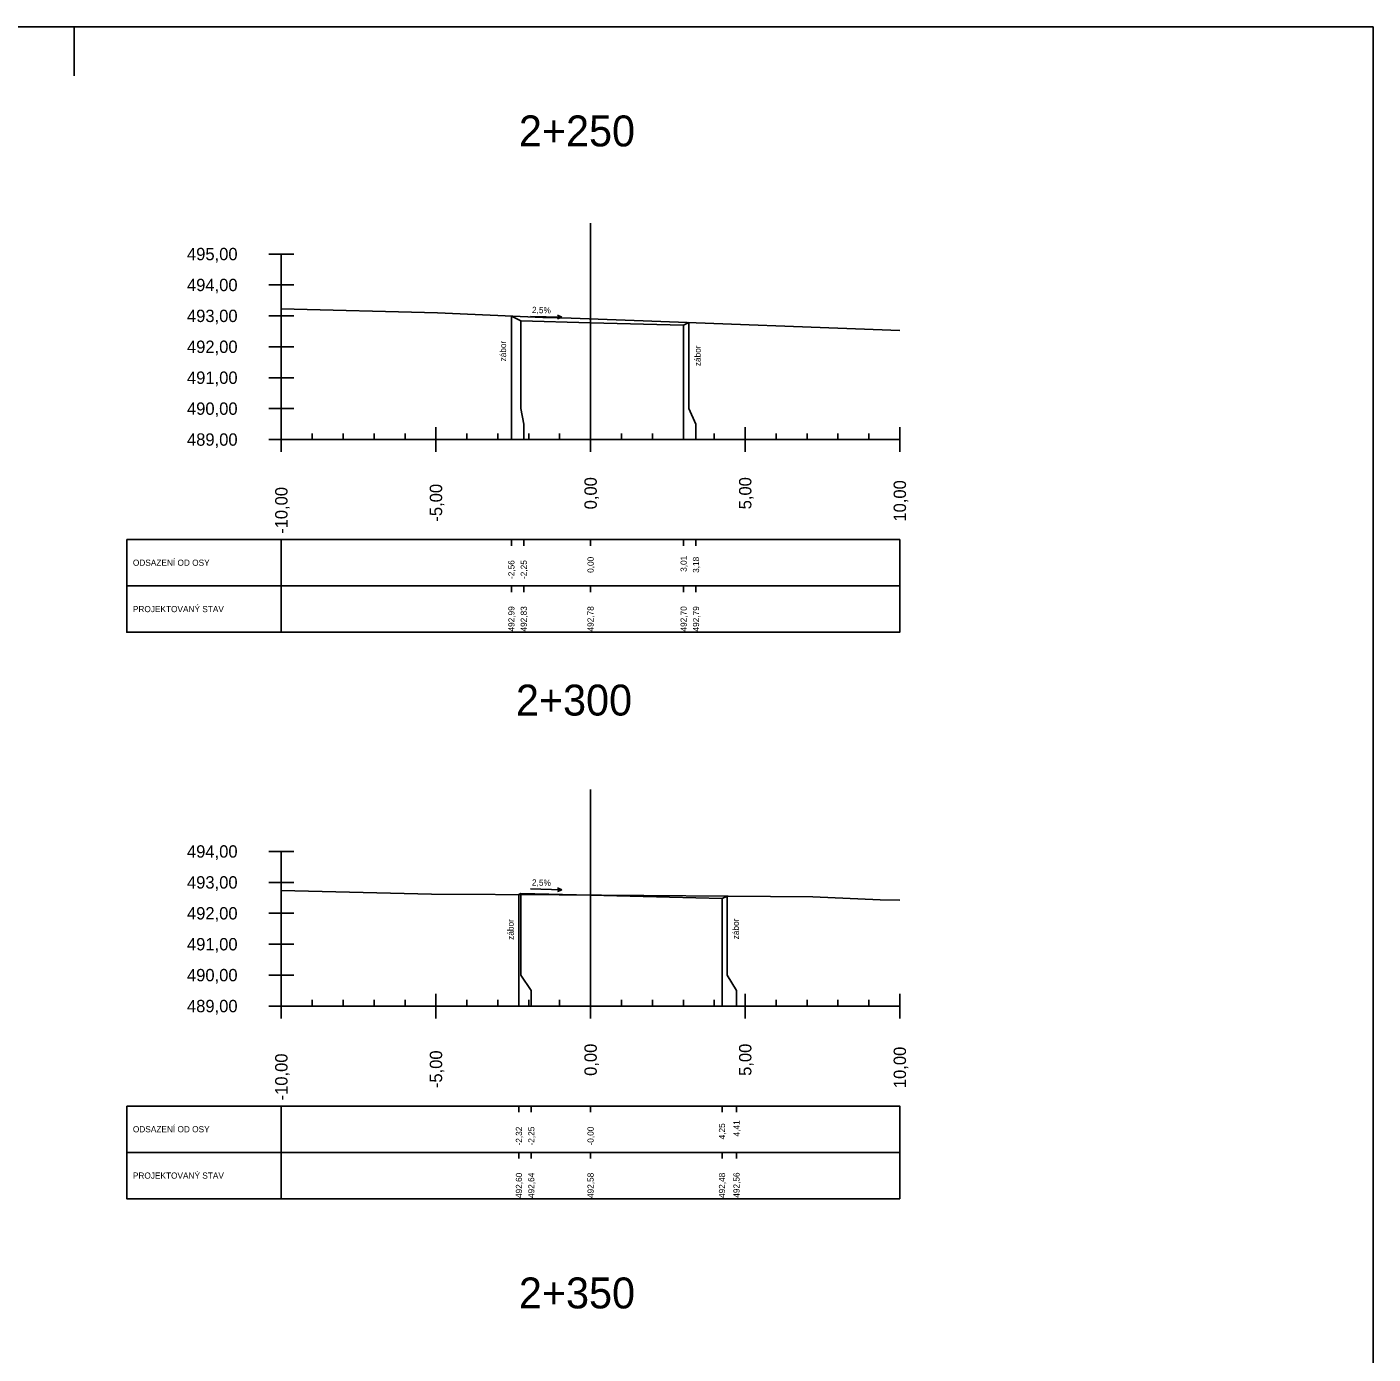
# Model space of a CAD drawing. Extents: x -631407 to -631215, y -1089700 to -1088598.
# Drawn here: x -631258.91 to -631215.38, y -1088808.16 to -1088765.23 of the extents above; entities that cross this region are included whole.
import ezdxf

# ---------------------------------------------------------------- set-up
doc = ezdxf.new("R2010")
doc.units = 0
for name, color, linetype in [('08_LEGENDA_HV', 7, 'Continuous'), ('59', 7, 'Continuous'), ('DTM-Breaklines', 7, 'Continuous'), ('NIVELETA_VYSKY', 7, 'Continuous'), ('REZ_BODY', 7, 'Continuous'), ('REZ_ODSTUPY', 7, 'Continuous'), ('REZ_POPIS', 7, 'Continuous'), ('REZ_RAMY', 7, 'Continuous'), ('REZ_STANICENI', 7, 'Continuous'), ('REZ_SVISLE', 7, 'Continuous'), ('REZ_TENKA', 7, 'Continuous'), ('REZ_TLUSTA', 7, 'Continuous'), ('TABULKA_POPIS', 7, 'Continuous'), ('TEREN', 7, 'Continuous'), ('zábor', 7, 'Continuous')]:
    doc.layers.add(name, color=color, linetype=linetype)

msp = doc.modelspace()

# ---------------------------------------------------------------- linework, layer by layer
at = {"layer": '08_LEGENDA_HV'}
msp.add_lwpolyline([(-631215.384, -1088943.435), (-631215.384, -1088765.235), (-631407.014, -1088765.235), (-631407.014, -1088943.435)], close=True, dxfattribs=at)
at = {"layer": '59'}
for p, q in [((-631251.088, -1088772.581), (-631250.288, -1088772.581)), ((-631250.688, -1088772.581), (-631250.688, -1088778.581)), ((-631251.088, -1088773.581), (-631250.288, -1088773.581)), ((-631251.088, -1088774.581), (-631250.288, -1088774.581)), ((-631251.088, -1088775.581), (-631250.288, -1088775.581)), ((-631251.088, -1088776.581), (-631250.288, -1088776.581)), ((-631251.088, -1088777.581), (-631250.288, -1088777.581)), ((-631251.088, -1088778.581), (-631250.288, -1088778.581)), ((-631251.088, -1088791.905), (-631250.288, -1088791.905)), ((-631250.688, -1088791.905), (-631250.688, -1088796.905)), ((-631251.088, -1088792.905), (-631250.288, -1088792.905)), ((-631251.088, -1088793.905), (-631250.288, -1088793.905)), ((-631251.088, -1088794.905), (-631250.288, -1088794.905)), ((-631251.088, -1088795.905), (-631250.288, -1088795.905)), ((-631251.088, -1088796.905), (-631250.288, -1088796.905))]:
    msp.add_line(p, q, dxfattribs=at)
at = {"layer": 'DTM-Breaklines'}
msp.add_line((-631257.384, -1088766.815), (-631257.384, -1088765.235), dxfattribs=at)
at = {"layer": 'REZ_RAMY'}
for p, q in [((-631255.688, -1088781.815), (-631255.688, -1088784.815)), ((-631250.688, -1088781.815), (-631250.688, -1088784.815)), ((-631243.249, -1088782.015), (-631243.249, -1088781.815)), ((-631242.849, -1088782.015), (-631242.849, -1088781.815)), ((-631240.688, -1088782.015), (-631240.688, -1088781.815)), ((-631237.679, -1088782.015), (-631237.679, -1088781.815)), ((-631237.279, -1088782.015), (-631237.279, -1088781.815)), ((-631255.688, -1088783.315), (-631230.688, -1088783.315)), ((-631243.249, -1088783.515), (-631243.249, -1088783.315)), ((-631242.849, -1088783.515), (-631242.849, -1088783.315)), ((-631240.688, -1088783.515), (-631240.688, -1088783.315)), ((-631237.679, -1088783.515), (-631237.679, -1088783.315)), ((-631237.279, -1088783.515), (-631237.279, -1088783.315)), ((-631255.688, -1088800.139), (-631255.688, -1088803.139)), ((-631250.688, -1088800.139), (-631250.688, -1088803.139)), ((-631243.005, -1088800.339), (-631243.005, -1088800.139)), ((-631242.605, -1088800.339), (-631242.605, -1088800.139)), ((-631240.688, -1088800.339), (-631240.688, -1088800.139)), ((-631236.438, -1088800.339), (-631236.438, -1088800.139)), ((-631235.97, -1088800.339), (-631235.97, -1088800.139)), ((-631255.688, -1088801.639), (-631230.688, -1088801.639)), ((-631243.005, -1088801.839), (-631243.005, -1088801.639)), ((-631242.605, -1088801.839), (-631242.605, -1088801.639)), ((-631240.688, -1088801.839), (-631240.688, -1088801.639)), ((-631236.438, -1088801.839), (-631236.438, -1088801.639)), ((-631235.97, -1088801.839), (-631235.97, -1088801.639))]:
    msp.add_line(p, q, dxfattribs=at)
for points in [[(-631255.688, -1088781.815), (-631255.688, -1088784.815), (-631230.688, -1088784.815), (-631230.688, -1088781.815)], [(-631255.688, -1088800.139), (-631255.688, -1088803.139), (-631230.688, -1088803.139), (-631230.688, -1088800.139)]]:
    msp.add_lwpolyline(points, close=True, dxfattribs=at)
at = {"layer": 'REZ_SVISLE'}
for points in [[(-631243.249, -1088774.591), (-631243.249, -1088777.581), (-631243.249, -1088778.081), (-631243.249, -1088778.581)], [(-631242.938, -1088774.747), (-631242.938, -1088777.581), (-631242.849, -1088778.081), (-631242.849, -1088778.581)], [(-631240.688, -1088774.804), (-631240.688, -1088777.581), (-631240.688, -1088778.081), (-631240.688, -1088778.581)], [(-631237.679, -1088774.879), (-631237.679, -1088777.581), (-631237.679, -1088778.081), (-631237.679, -1088778.581)], [(-631237.51, -1088774.794), (-631237.51, -1088777.581), (-631237.279, -1088778.081), (-631237.279, -1088778.581)], [(-631243.005, -1088793.301), (-631243.005, -1088795.905), (-631243.005, -1088796.405), (-631243.005, -1088796.905)], [(-631242.938, -1088793.267), (-631242.938, -1088795.905), (-631242.605, -1088796.405), (-631242.605, -1088796.905)], [(-631240.688, -1088793.323), (-631240.688, -1088795.905), (-631240.688, -1088796.405), (-631240.688, -1088796.905)], [(-631236.438, -1088793.429), (-631236.438, -1088795.905), (-631236.438, -1088796.405), (-631236.438, -1088796.905)], [(-631236.275, -1088793.348), (-631236.275, -1088795.905), (-631235.97, -1088796.405), (-631235.97, -1088796.905)]]:
    msp.add_lwpolyline(points, dxfattribs=at)
at = {"layer": 'REZ_TENKA'}
for p, q in [((-631249.688, -1088778.581), (-631249.688, -1088778.381)), ((-631248.688, -1088778.581), (-631248.688, -1088778.381)), ((-631247.688, -1088778.581), (-631247.688, -1088778.381)), ((-631246.688, -1088778.581), (-631246.688, -1088778.381)), ((-631244.688, -1088778.581), (-631244.688, -1088778.381)), ((-631243.688, -1088778.581), (-631243.688, -1088778.381)), ((-631242.688, -1088778.581), (-631242.688, -1088778.381)), ((-631241.688, -1088778.581), (-631241.688, -1088778.381)), ((-631239.688, -1088778.581), (-631239.688, -1088778.381)), ((-631238.688, -1088778.581), (-631238.688, -1088778.381)), ((-631237.688, -1088778.581), (-631237.688, -1088778.381)), ((-631236.688, -1088778.581), (-631236.688, -1088778.381)), ((-631234.688, -1088778.581), (-631234.688, -1088778.381)), ((-631233.688, -1088778.581), (-631233.688, -1088778.381)), ((-631232.688, -1088778.581), (-631232.688, -1088778.381)), ((-631231.688, -1088778.581), (-631231.688, -1088778.381)), ((-631249.688, -1088796.905), (-631249.688, -1088796.705)), ((-631248.688, -1088796.905), (-631248.688, -1088796.705)), ((-631247.688, -1088796.905), (-631247.688, -1088796.705)), ((-631246.688, -1088796.905), (-631246.688, -1088796.705)), ((-631244.688, -1088796.905), (-631244.688, -1088796.705)), ((-631243.688, -1088796.905), (-631243.688, -1088796.705)), ((-631242.688, -1088796.905), (-631242.688, -1088796.705)), ((-631241.688, -1088796.905), (-631241.688, -1088796.705)), ((-631239.688, -1088796.905), (-631239.688, -1088796.705)), ((-631238.688, -1088796.905), (-631238.688, -1088796.705)), ((-631237.688, -1088796.905), (-631237.688, -1088796.705)), ((-631236.688, -1088796.905), (-631236.688, -1088796.705)), ((-631234.688, -1088796.905), (-631234.688, -1088796.705)), ((-631233.688, -1088796.905), (-631233.688, -1088796.705)), ((-631232.688, -1088796.905), (-631232.688, -1088796.705)), ((-631231.688, -1088796.905), (-631231.688, -1088796.705))]:
    msp.add_line(p, q, dxfattribs=at)
at = {"layer": 'REZ_TLUSTA'}
for p, q in [((-631240.688, -1088771.581), (-631240.688, -1088778.581)), ((-631250.688, -1088778.981), (-631250.688, -1088778.181)), ((-631245.688, -1088778.981), (-631245.688, -1088778.181)), ((-631240.688, -1088778.981), (-631240.688, -1088778.181)), ((-631235.688, -1088778.981), (-631235.688, -1088778.181)), ((-631230.688, -1088778.981), (-631230.688, -1088778.181)), ((-631250.688, -1088778.581), (-631230.688, -1088778.581)), ((-631240.688, -1088789.905), (-631240.688, -1088796.905)), ((-631250.688, -1088797.305), (-631250.688, -1088796.505)), ((-631245.688, -1088797.305), (-631245.688, -1088796.505)), ((-631240.688, -1088797.305), (-631240.688, -1088796.505)), ((-631235.688, -1088797.305), (-631235.688, -1088796.505)), ((-631230.688, -1088797.305), (-631230.688, -1088796.505)), ((-631250.688, -1088796.905), (-631230.688, -1088796.905))]:
    msp.add_line(p, q, dxfattribs=at)
at = {"layer": 'TEREN'}
for points in [[(-631250.688, -1088774.357), (-631245.637, -1088774.488), (-631242.231, -1088774.636), (-631241.321, -1088774.655), (-631239.282, -1088774.726), (-631230.688, -1088775.056)], [(-631243.249, -1088774.591), (-631242.938, -1088774.747), (-631240.688, -1088774.804), (-631237.679, -1088774.879), (-631237.51, -1088774.794)], [(-631250.688, -1088793.166), (-631245.835, -1088793.29), (-631241.701, -1088793.305), (-631233.506, -1088793.37), (-631231.322, -1088793.47), (-631230.688, -1088793.484)], [(-631243.005, -1088793.301), (-631242.938, -1088793.267), (-631240.688, -1088793.323), (-631236.438, -1088793.429), (-631236.275, -1088793.348)]]:
    msp.add_lwpolyline(points, dxfattribs=at)
at = {"layer": 'zábor'}
for p, q in [((-631241.621, -1088774.624), (-631242.629, -1088774.599)), ((-631241.621, -1088774.624), (-631241.76, -1088774.682)), ((-631241.621, -1088774.624), (-631241.757, -1088774.559)), ((-631241.621, -1088793.143), (-631242.629, -1088793.118)), ((-631241.621, -1088793.143), (-631241.76, -1088793.201)), ((-631241.621, -1088793.143), (-631241.757, -1088793.079))]:
    msp.add_line(p, q, dxfattribs=at)

# ---------------------------------------------------------------- texts
at = {"layer": 'NIVELETA_VYSKY'}
for s, p in [('492,99', (-631243.149, -1088784.791)), ('492,83', (-631242.749, -1088784.791)), ('492,78', (-631240.588, -1088784.791)), ('492,70', (-631237.579, -1088784.791)), ('492,79', (-631237.179, -1088784.791)), ('492,60', (-631242.905, -1088803.115)), ('492,64', (-631242.505, -1088803.115)), ('492,58', (-631240.588, -1088803.115)), ('492,48', (-631236.338, -1088803.115)), ('492,56', (-631235.87, -1088803.105))]:
    msp.add_text(s, height=0.2, rotation=90, dxfattribs=at).set_placement(p)
at = {"layer": 'REZ_BODY'}
for s, p in [('3,01', (-631237.579, -1088782.861)), ('-2,56', (-631243.149, -1088783.092)), ('-2,25', (-631242.749, -1088783.092)), ('0,00', (-631240.588, -1088782.894)), ('3,18', (-631237.179, -1088782.894)), ('4,41', (-631235.87, -1088801.123)), ('-2,32', (-631242.905, -1088801.416)), ('-2,25', (-631242.505, -1088801.416)), ('-0,00', (-631240.588, -1088801.416)), ('4,25', (-631236.338, -1088801.218))]:
    msp.add_text(s, height=0.2, rotation=90, dxfattribs=at).set_placement(p)
at = {"layer": 'REZ_ODSTUPY'}
for s, p in [('-10,00', (-631250.488, -1088781.633)), ('-5,00', (-631245.488, -1088781.236)), ('0,00', (-631240.488, -1088780.839)), ('5,00', (-631235.488, -1088780.839)), ('10,00', (-631230.488, -1088781.236)), ('-10,00', (-631250.488, -1088799.957)), ('-5,00', (-631245.488, -1088799.56)), ('0,00', (-631240.488, -1088799.164)), ('5,00', (-631235.488, -1088799.164)), ('10,00', (-631230.488, -1088799.56))]:
    msp.add_text(s, height=0.4, rotation=90, dxfattribs=at).set_placement(p)
at = {"layer": 'REZ_POPIS'}
for s, p in [('495,00', (-631253.739, -1088772.781)), ('494,00', (-631253.739, -1088773.781)), ('493,00', (-631253.739, -1088774.781)), ('492,00', (-631253.739, -1088775.781)), ('491,00', (-631253.739, -1088776.781)), ('490,00', (-631253.739, -1088777.781)), ('489,00', (-631253.739, -1088778.781)), ('494,00', (-631253.739, -1088792.105)), ('493,00', (-631253.739, -1088793.105)), ('492,00', (-631253.739, -1088794.105)), ('491,00', (-631253.739, -1088795.105)), ('490,00', (-631253.739, -1088796.105)), ('489,00', (-631253.739, -1088797.105))]:
    msp.add_text(s, height=0.4, dxfattribs=at).set_placement(p)
at = {"layer": 'REZ_STANICENI'}
for s, p in [('2+250', (-631243.006, -1088769.099)), ('2+300', (-631243.102, -1088787.509)), ('2+350', (-631243.006, -1088806.685))]:
    msp.add_text(s, height=1, dxfattribs=at).set_placement(p)
at = {"layer": 'TABULKA_POPIS'}
for s, p in [('ODSAZENÍ OD OSY', (-631255.488, -1088782.665)), ('PROJEKTOVANÝ STAV', (-631255.488, -1088784.165)), ('ODSAZENÍ OD OSY', (-631255.488, -1088800.989)), ('PROJEKTOVANÝ STAV', (-631255.488, -1088802.489))]:
    msp.add_text(s, height=0.2, dxfattribs=at).set_placement(p)
at = {"layer": 'zábor'}
for s, rotation, p in [('2,5%', 358.5679, (-631242.584, -1088774.487)), ('zábor', 90, (-631243.419, -1088776.055)), ('zábor', 90, (-631237.127, -1088776.208)), ('2,5%', 358.5679, (-631242.584, -1088793.006)), ('zábor', 90, (-631243.175, -1088794.764)), ('zábor', 90, (-631235.893, -1088794.746))]:
    msp.add_text(s, height=0.2, rotation=rotation, dxfattribs=at).set_placement(p)

doc.saveas('drawing.dxf')
